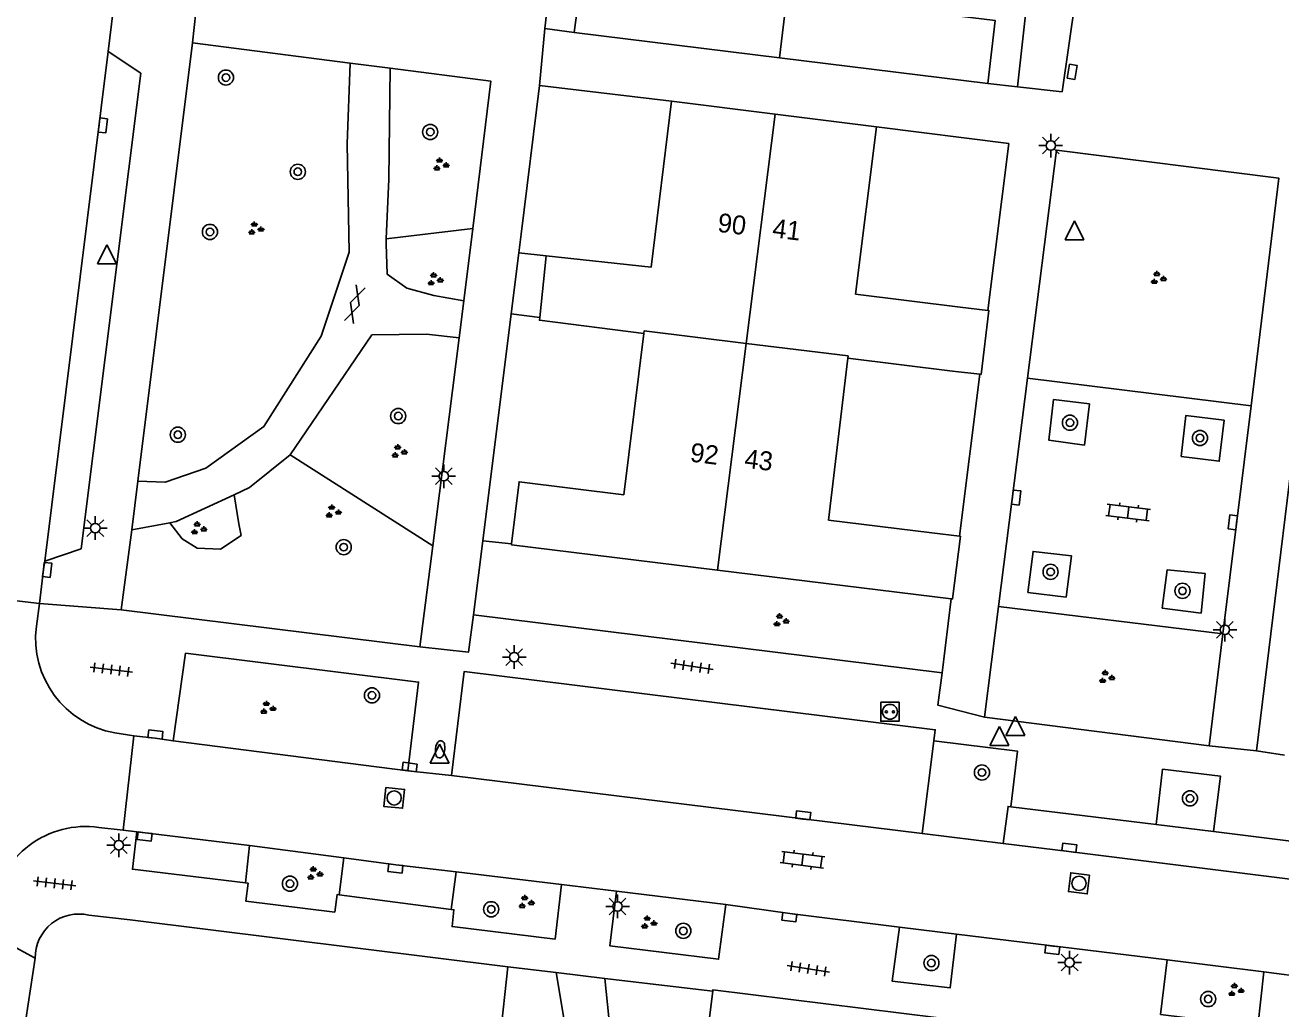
# Model space of a CAD drawing. Extents: x 131000 to 133014, y 396499 to 399001.
# Drawn here: x 131362.8 to 131429.2, y 396813.1 to 396865 of the extents above; entities that cross this region are included whole.
import ezdxf

# ---------------------------------------------------------------- set-up
doc = ezdxf.new("R2010")
doc.units = 0
for name, color, linetype in [('gg-afsc-erfafscheiding', 7, 'Continuous'), ('gg-afsc-hekwerk', 7, 'Continuous'), ('gg-afsc-muur', 7, 'Continuous'), ('gg-anno-huisnummerreeks BGT', 7, 'Continuous'), ('gg-bbg-hoofdgebouw', 7, 'Continuous'), ('gg-bbg-tussenscheiding', 7, 'Continuous'), ('gg-knt-verharding', 7, 'Continuous'), ('gg-knt-verharding nz', 7, 'Continuous'), ('gt-grn-groengrens', 7, 'Continuous'), ('gt-grn-weggrens', 7, 'Continuous'), ('gt-symb-boom', 7, 'Continuous'), ('gt-symb-brandkraan', 7, 'Continuous'), ('gt-symb-gesloten verharding', 7, 'Continuous'), ('gt-symb-groenvak', 7, 'Continuous'), ('gt-symb-klinker verharding', 7, 'Continuous'), ('gt-symb-kolk', 7, 'Continuous'), ('gt-symb-kolk center center', 7, 'Continuous'), ('gt-symb-laadpunt elektrisch vervoer', 7, 'Continuous'), ('gt-symb-lichtmast', 7, 'Continuous'), ('gt-symb-rioolschacht', 7, 'Continuous'), ('gt-symb-tegel verharding', 7, 'Continuous'), ('gt-symb-waterafsluiter', 7, 'Continuous')]:
    doc.layers.add(name, color=color, linetype=linetype)

# ---------------------------------------------------------------- blocks, each defined once
blk = doc.blocks.new('gt0-BOOM')
at = {"layer": 'gt-symb-boom'}
for radius in [0.4, 0.2]:
    blk.add_circle((0, 0), radius, dxfattribs=at)
blk = doc.blocks.new('gt0-GRVAK')
at = {"layer": 'gt-symb-groenvak'}
for p, q in [((-0.11, 0.189), (-0.228, 0.24)), ((-0.182, 0.153), (0.088, 0.153)), ((-0.091, 0.211), (-0.156, 0.322)), ((-0.047, 0.214), (-0.047, 0.393)), ((-0.004, 0.211), (0.061, 0.322)), ((0.015, 0.189), (0.133, 0.24)), ((0.262, -0.052), (0.197, 0.059)), ((0.305, -0.049), (0.305, 0.13)), ((0.349, -0.052), (0.414, 0.059)), ((-0.245, -0.228), (-0.363, -0.177)), ((-0.318, -0.264), (-0.047, -0.264)), ((-0.226, -0.206), (-0.291, -0.095)), ((-0.183, -0.203), (-0.183, -0.024)), ((-0.139, -0.206), (-0.074, -0.095)), ((-0.12, -0.228), (-0.002, -0.177)), ((0.243, -0.074), (0.125, -0.023)), ((0.17, -0.11), (0.441, -0.11)), ((0.368, -0.074), (0.486, -0.023))]:
    blk.add_line(p, q, dxfattribs=at)
blk = doc.blocks.new('gt0-LMAST')
at = {"layer": 'gt-symb-lichtmast'}
for p, q in [((-0.182, 0.173), (-0.447, 0.438)), ((-0.005, 0.246), (-0.005, 0.621)), ((0.172, 0.173), (0.437, 0.438)), ((-0.255, -0.004), (-0.63, -0.004)), ((-0.182, -0.181), (-0.447, -0.446)), ((-0.005, -0.254), (-0.005, -0.629)), ((0.437, -0.446), (0.172, -0.181)), ((0.245, -0.004), (0.62, -0.004))]:
    blk.add_line(p, q, dxfattribs=at)
blk.add_circle((-0.005, -0.004), 0.25, dxfattribs=at)
blk = doc.blocks.new('gt0-KOLK')
at = {"layer": 'gt-symb-kolk'}
blk.add_lwpolyline([(0, 0), (0.375, 0), (0.375, 0.4), (-0.375, 0.4), (-0.375, 0), (0, 0)], dxfattribs=at)
blk = doc.blocks.new('gt0-KL1')
at = {"layer": 'gt-symb-klinker verharding'}
for p, q in [((-1.15, 0.3), (1.15, 0.3)), ((-1, -0.3), (-1, 0.3)), ((-0.5, 0.3), (-0.5, 0.45)), ((0, -0.3), (0, 0.3)), ((0.5, 0.3), (0.5, 0.45)), ((1, -0.3), (1, 0.3)), ((-1.15, -0.3), (1.15, -0.3)), ((-0.5, -0.45), (-0.5, -0.3)), ((0.5, -0.45), (0.5, -0.3))]:
    blk.add_line(p, q, dxfattribs=at)
blk = doc.blocks.new('gt0-WAFSL')
at = {"layer": 'gt-symb-waterafsluiter'}
for p, q in [((-0.5, -0.333), (0, 0.667)), ((0, 0.667), (0.5, -0.333)), ((0.5, -0.333), (-0.5, -0.333))]:
    blk.add_line(p, q, dxfattribs=at)
blk = doc.blocks.new('gt0-KOLKCC')
at = {"layer": 'gt-symb-kolk center center'}
blk.add_lwpolyline([(-0.375, 0.2), (0.375, 0.2), (0.375, -0.2), (-0.375, -0.2)], close=True, dxfattribs=at)
blk = doc.blocks.new('gt0-RS')
at = {"layer": 'gt-symb-rioolschacht'}
blk.add_lwpolyline([(-0.5, -0.5), (0.5, -0.5), (0.5, 0.5), (-0.5, 0.5)], close=True, dxfattribs=at)
blk.add_circle((0, 0), 0.375, dxfattribs=at)
blk = doc.blocks.new('gt0-TEG1')
at = {"layer": 'gt-symb-tegel verharding'}
for p, q in [((-1.125, 0), (1.125, 0)), ((-0.9, -0.25), (-0.9, 0.25)), ((-0.45, -0.25), (-0.45, 0.25)), ((0, -0.25), (0, 0.25)), ((0.45, -0.25), (0.45, 0.25)), ((0.9, -0.25), (0.9, 0.25))]:
    blk.add_line(p, q, dxfattribs=at)
blk = doc.blocks.new('gt0-LEV')
at = {"layer": 'gt-symb-laadpunt elektrisch vervoer'}
blk.add_lwpolyline([(-0.486, 0.501), (0.486, 0.501), (0.486, -0.499), (-0.486, -0.499)], close=True, dxfattribs=at)
for centre, radius in [((0, 0), 0.393), ((-0.186, 0), 0.0566), ((0.186, 0), 0.0566)]:
    blk.add_circle(centre, radius, dxfattribs=at)
blk = doc.blocks.new('gt0-BR')
at = {"layer": 'gt-symb-brandkraan'}
for centre, radius, start, end in [((-0.244, 0), 0.206, 107.56694, 252.43307), ((0.599, -2.664), 3, 106.89205, 107.56694), ((0, -0.691), 0.938, 73.10799, 106.89205), ((-0.599, -2.664), 3, 72.43309, 73.10799), ((0.244, 0), 0.206, 287.56695, 72.43309), ((0.599, 2.664), 3, 252.43307, 253.10797), ((0, 0.691), 0.938, 253.10797, 286.89206), ((-0.599, 2.664), 3, 286.89206, 287.56695)]:
    blk.add_arc(centre, radius, start, end, dxfattribs=at)
blk = doc.blocks.new('gt0-GESVH1')
at = {"layer": 'gt-symb-gesloten verharding'}
for p, q in [((-0.992, -0.261), (0.008, 0.239)), ((0.008, -0.261), (-0.992, 0.239)), ((0.008, 0.239), (1.008, -0.261)), ((1.008, 0.239), (0.008, -0.261))]:
    blk.add_line(p, q, dxfattribs=at)

msp = doc.modelspace()

# ---------------------------------------------------------------- linework, layer by layer
at = {"layer": 'gg-afsc-erfafscheiding'}
for p, q in [((131397.74, 396924.6), (131390.25, 396864.87)), ((131390.25, 396864.87), (131391.81, 396864.65)), ((131414.77, 396858.79), (131413.664, 396849.974)), ((131430.695, 396849.868), (131427.87, 396826.7)), ((131413.24, 396846.596), (131412.167, 396838.045)), ((131427.87, 396826.7), (131429.35, 396826.47))]:
    msp.add_line(p, q, dxfattribs=at)
at = {"layer": 'gg-afsc-hekwerk'}
for p, q in [((131368.347, 396817.779), (131388.304, 396815.302)), ((131388.304, 396815.302), (131387.67, 396809.42))]:
    msp.add_line(p, q, dxfattribs=at)
at = {"layer": 'gg-afsc-muur'}
for p, q in [((131389.98, 396861.86), (131389.002, 396854)), ((131396.96, 396861.02), (131389.98, 396861.86)), ((131407.79, 396859.66), (131414.77, 396858.79)), ((131388.478, 396849.788), (131388.879, 396853.007)), ((131390.33, 396852.85), (131388.879, 396853.007)), ((131389.986, 396849.599), (131388.478, 396849.788))]:
    msp.add_line(p, q, dxfattribs=at)
at = {"layer": 'gg-bbg-hoofdgebouw'}
for p, q in [((131391.81, 396864.65), (131402.651, 396863.316)), ((131402.651, 396863.316), (131413.67, 396861.96)), ((131396.96, 396861.02), (131402.438, 396860.332)), ((131402.438, 396860.332), (131407.79, 396859.66)), ((131390.33, 396852.85), (131389.986, 396849.599)), ((131413.664, 396849.974), (131412.21, 396850.15)), ((131406.27, 396847.44), (131411.8, 396846.77)), ((131411.8, 396846.77), (131413.24, 396846.596)), ((131412.167, 396838.045), (131410.71, 396838.23)), ((131399.391, 396836.255), (131411.73, 396834.737))]:
    msp.add_line(p, q, dxfattribs=at)
for points in [[(131398.84, 396875.89), (131397.82, 396867.35), (131392.25, 396867.95), (131391.81, 396864.65)], [(131413.67, 396861.96), (131414.06, 396865.28), (131408.54, 396865.96), (131409.6, 396874.5)], [(131396.96, 396861.02), (131395.87, 396852.25), (131390.33, 396852.85)], [(131412.21, 396850.15), (131406.68, 396850.83), (131407.79, 396859.66)], [(131389.986, 396849.599), (131389.97, 396849.45), (131395.49, 396848.76)], [(131413.24, 396846.596), (131413.31, 396846.587), (131413.72, 396849.967), (131413.664, 396849.974)], [(131395.49, 396848.76), (131394.43, 396840.23), (131388.9, 396840.92), (131388.497, 396837.648)], [(131410.71, 396838.23), (131405.25, 396838.9), (131406.27, 396847.44)], [(131388.497, 396837.648), (131388.49, 396837.59), (131399.391, 396836.255)], [(131411.73, 396834.737), (131411.801, 396834.728), (131412.221, 396838.038), (131412.167, 396838.045)], [(131399.13, 396814.01), (131396.65, 396794.23), (131403.55, 396793.37)], [(131415.066, 396812.112), (131399.14, 396814.09), (131399.13, 396814.01)]]:
    msp.add_lwpolyline(points, dxfattribs=at)
at = {"layer": 'gg-bbg-tussenscheiding'}
for p, q in [((131404.122, 396875.241), (131402.651, 396863.316)), ((131402.438, 396860.332), (131400.906, 396848.228)), ((131400.906, 396848.228), (131399.391, 396836.255))]:
    msp.add_line(p, q, dxfattribs=at)
for points in [[(131400.906, 396848.228), (131395.506, 396848.889), (131395.49, 396848.76)], [(131400.906, 396848.228), (131406.285, 396847.569), (131406.27, 396847.44)]]:
    msp.add_lwpolyline(points, dxfattribs=at)
at = {"layer": 'gg-knt-verharding'}
for p, q in [((131367.182, 396863.652), (131367.798, 396868.619)), ((131415.79, 396866.747), (131415.234, 396861.783)), ((131368.757, 396840.943), (131371.64, 396864.1)), ((131371.64, 396864.1), (131379.966, 396863.033)), ((131379.966, 396863.033), (131382.084, 396862.762)), ((131415.234, 396861.783), (131413.67, 396861.96)), ((131385.971, 396850.479), (131386.445, 396854.302)), ((131388.879, 396853.007), (131389.002, 396854)), ((131385.971, 396850.479), (131385.727, 396848.514)), ((131386.976, 396837.801), (131388.478, 396849.788)), ((131384.333, 396837.53), (131385.727, 396848.514)), ((131414.24, 396834.33), (131415.77, 396846.4)), ((131415.77, 396846.4), (131427.59, 396844.93)), ((131427.59, 396844.93), (131426.08, 396832.89)), ((131368.438, 396838.379), (131368.757, 396840.943)), ((131368.438, 396838.379), (131367.866, 396834.16)), ((131368.438, 396838.379), (131370.435, 396838.752)), ((131383.657, 396832.201), (131384.333, 396837.53)), ((131386.487, 396833.899), (131386.976, 396837.801)), ((131388.497, 396837.648), (131386.976, 396837.801)), ((131356.473, 396835.344), (131363.548, 396834.487)), ((131363.548, 396834.487), (131363.387, 396833.286)), ((131411.73, 396834.737), (131411.248, 396830.823)), ((131413.5, 396828.48), (131414.24, 396834.33)), ((131426.08, 396832.89), (131414.24, 396834.33)), ((131367.866, 396834.16), (131383.657, 396832.201)), ((131411.248, 396830.823), (131386.487, 396833.899)), ((131426.08, 396832.89), (131425.37, 396826.97)), ((131425.37, 396826.97), (131413.5, 396828.48)), ((131367.539, 396827.657), (131368.542, 396827.5)), ((131367.969, 396822.519), (131368.542, 396827.5)), ((131383.013, 396825.658), (131370.617, 396827.235)), ((131410.813, 396827.237), (131410.19, 396822.336)), ((131385.332, 396825.401), (131383.013, 396825.658)), ((131414.886, 396823.751), (131422.563, 396822.82)), ((131367.969, 396822.519), (131366.684, 396822.66)), ((131368.689, 396822.434), (131367.969, 396822.519)), ((131410.19, 396822.336), (131414.479, 396821.807)), ((131425.592, 396822.452), (131422.563, 396822.82)), ((131425.592, 396822.452), (131432.988, 396821.525)), ((131374.657, 396821.706), (131374.435, 396819.73)), ((131379.64, 396821.064), (131374.657, 396821.706)), ((131379.395, 396819.095), (131379.64, 396821.064)), ((131385.307, 396818.332), (131385.571, 396820.322)), ((131385.571, 396820.322), (131391.137, 396819.642)), ((131391.137, 396819.642), (131394.042, 396819.299)), ((131385.307, 396818.332), (131379.395, 396819.095)), ((131394.042, 396819.299), (131399.823, 396818.593)), ((131366.16, 396818.027), (131368.347, 396817.779)), ((131408.992, 396817.396), (131412.006, 396817.025)), ((131412.006, 396817.025), (131423.151, 396815.659)), ((131362.826, 396812.521), (131363.324, 396815.75)), ((131423.151, 396815.659), (131428.255, 396815.027)), ((131388.304, 396815.302), (131390.854, 396814.998)), ((131390.854, 396814.998), (131393.43, 396814.69)), ((131428.255, 396815.027), (131439.526, 396813.605)), ((131393.43, 396814.69), (131399.13, 396814.01))]:
    msp.add_line(p, q, dxfattribs=at)
for points in [[(131415.234, 396861.783), (131417.592, 396861.518), (131418.293, 396866.436), (131415.79, 396866.747)], [(131363.84, 396836.732), (131365.753, 396837.383), (131368.908, 396862.502), (131367.182, 396863.652)], [(131379.966, 396863.033), (131379.805, 396858.763), (131379.911, 396853.052), (131378.433, 396848.607), (131375.414, 396843.839), (131372.337, 396841.634), (131370.201, 396840.907), (131368.757, 396840.943)], [(131381.876, 396853.758), (131382.007, 396856.908), (131382.084, 396862.762)], [(131386.445, 396854.302), (131387.41, 396862.08), (131382.084, 396862.762)], [(131415.77, 396846.4), (131417.29, 396858.44), (131429.04, 396856.96), (131427.59, 396844.93)], [(131385.971, 396850.479), (131384.386, 396850.761), (131382.971, 396851.15), (131381.933, 396851.884), (131381.865, 396853.493), (131381.876, 396853.758)], [(131376.804, 396842.335), (131381.117, 396848.676), (131384.012, 396848.724), (131385.727, 396848.514)], [(131418.775, 396842.861), (131416.895, 396843.112), (131417.146, 396845.259), (131419.033, 396845.029), (131418.775, 396842.861)], [(131423.876, 396842.258), (131425.899, 396842.001), (131426.157, 396844.166), (131424.134, 396844.423), (131423.876, 396842.258)], [(131373.838, 396840.238), (131374.648, 396840.615), (131376.804, 396842.335)], [(131370.435, 396838.752), (131370.783, 396838.817), (131373.838, 396840.238)], [(131415.779, 396835.075), (131416.057, 396837.245), (131418.09, 396837.002), (131417.802, 396834.832), (131415.779, 396835.075)], [(131363.548, 396834.487), (131363.764, 396836.289), (131363.84, 396836.732)], [(131422.878, 396834.251), (131423.146, 396836.276), (131425.146, 396836.074), (131424.936, 396833.983), (131422.878, 396834.251)], [(131370.617, 396827.235), (131371.273, 396831.863), (131383.584, 396830.34), (131383.013, 396825.658)], [(131385.332, 396825.401), (131385.992, 396830.893), (131410.887, 396827.817), (131410.813, 396827.237)], [(131368.542, 396827.5), (131369.66, 396827.372), (131370.617, 396827.235)], [(131414.886, 396823.751), (131415.23, 396826.695), (131410.813, 396827.237)], [(131422.563, 396822.82), (131422.906, 396825.738), (131425.959, 396825.374), (131425.592, 396822.452)], [(131414.479, 396821.807), (131414.742, 396823.768), (131414.886, 396823.751)], [(131374.435, 396819.73), (131368.464, 396820.449), (131368.689, 396822.434)], [(131379.395, 396819.095), (131379.277, 396819.11), (131379.157, 396818.192), (131374.451, 396818.767), (131374.573, 396819.713), (131374.435, 396819.73)], [(131391.137, 396819.642), (131390.796, 396816.763), (131385.355, 396817.423), (131385.453, 396818.313), (131385.307, 396818.332)], [(131399.823, 396818.593), (131399.443, 396815.699), (131393.694, 396816.406), (131394.042, 396819.299)], [(131399.823, 396818.593), (131403.206, 396818.115), (131408.992, 396817.396)], [(131412.006, 396817.025), (131411.673, 396814.182), (131408.619, 396814.539), (131408.992, 396817.396)], [(131428.255, 396815.027), (131427.934, 396812.146), (131422.798, 396812.784), (131423.151, 396815.659)], [(131390.854, 396814.998), (131392.07, 396807.72), (131392.4, 396803.51), (131392.37, 396800.36), (131392.264, 396799.866)], [(131392.37, 396792.3), (131393.26, 396795.58), (131393.85, 396797.56), (131394.36, 396800.24), (131394.46, 396802.02), (131394.46, 396804.43), (131394.28, 396807.55), (131393.87, 396810.39), (131393.43, 396814.69)]]:
    msp.add_lwpolyline(points, dxfattribs=at)
for centre, radius, start, end in [((131368.419, 396832.652), 5.072, 172.82054, 260.00509), ((131365.982, 396817.793), 4.917, 81.7975, 172.42739), ((131365.633, 396815.779), 2.309, 76.81358, 180.70778)]:
    msp.add_arc(centre, radius, start, end, dxfattribs=at)
at = {"layer": 'gg-knt-verharding nz'}
for p, q in [((131363.84, 396836.732), (131367.182, 396863.652)), ((131410.19, 396822.336), (131385.332, 396825.401)), ((131368.689, 396822.434), (131374.657, 396821.706))]:
    msp.add_line(p, q, dxfattribs=at)
for points in [[(131455.889, 396816.625), (131447.389, 396817.711), (131417.954, 396821.389), (131414.479, 396821.807)], [(131385.571, 396820.322), (131382.385, 396820.689), (131379.64, 396821.064)]]:
    msp.add_lwpolyline(points, dxfattribs=at)
at = {"layer": 'gt-grn-groengrens'}
for p, q in [((131381.876, 396853.758), (131386.445, 396854.302)), ((131384.333, 396837.53), (131376.804, 396842.335))]:
    msp.add_line(p, q, dxfattribs=at)
msp.add_lwpolyline([(131373.838, 396840.238), (131374.087, 396838.696), (131374.209, 396838.086), (131373.11, 396837.353), (131371.889, 396837.414), (131371.095, 396837.902), (131370.435, 396838.752)], dxfattribs=at)
at = {"layer": 'gt-grn-weggrens'}
for p, q in [((131371.98, 396867.21), (131371.64, 396864.1)), ((131389.98, 396861.86), (131390.25, 396864.87)), ((131363.548, 396834.487), (131367.866, 396834.16)), ((131425.37, 396826.97), (131427.87, 396826.7)), ((131360.896, 396817.057), (131363.324, 396815.75))]:
    msp.add_line(p, q, dxfattribs=at)
for points in [[(131383.657, 396832.201), (131386.221, 396831.914), (131386.487, 396833.899)], [(131413.5, 396828.48), (131411.022, 396829.123), (131411.248, 396830.823)]]:
    msp.add_lwpolyline(points, dxfattribs=at)

# ---------------------------------------------------------------- block references
at = {"layer": 'gt-symb-boom'}
for p in [(131373.405, 396862.27), (131384.202, 396859.396), (131377.204, 396857.294), (131372.56, 396854.116), (131418.006, 396844.04), (131370.864, 396843.405), (131424.878, 396843.232), (131379.629, 396837.465), (131416.984, 396836.16), (131423.955, 396835.158), (131381.122, 396829.636), (131413.358, 396825.563), (131424.349, 396824.196), (131376.788, 396819.69), (131387.423, 396818.338), (131397.577, 396817.196), (131410.687, 396815.498), (131425.311, 396813.595)]:
    msp.add_blockref('gt0-BOOM', p, dxfattribs=at)
at = {"layer": 'gt-symb-boom', "rotation": 82.8749836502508}
msp.add_blockref('gt0-BOOM', (131382.511, 396844.39), dxfattribs=at)
at = {"layer": 'gt-symb-brandkraan', "rotation": 83.3370363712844}
msp.add_blockref('gt0-BR', (131384.725, 396826.79), dxfattribs=at)
at = {"layer": 'gt-symb-gesloten verharding', "rotation": 71.5831655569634}
msp.add_blockref('gt0-GESVH1', (131380.204, 396850.298), dxfattribs=at)
at = {"layer": 'gt-symb-groenvak'}
for p in [(131384.737, 396857.664), (131374.953, 396854.282), (131384.43, 396851.597), (131422.648, 396851.667), (131382.529, 396842.509), (131379.045, 396839.33), (131371.931, 396838.445), (131402.709, 396833.587), (131419.919, 396830.592), (131375.589, 396828.962), (131378.071, 396820.216), (131389.242, 396818.704), (131395.717, 396817.624), (131426.746, 396814.061)]:
    msp.add_blockref('gt0-GRVAK', p, dxfattribs=at)
at = {"layer": 'gt-symb-klinker verharding'}
for p, rotation in [((131421.082, 396839.299), -7.068140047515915), ((131403.878, 396820.955), -7.125016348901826)]:
    msp.add_blockref('gt0-KL1', p, dxfattribs=dict(at, rotation=rotation))
at = {"layer": 'gt-symb-kolk'}
for p, rotation in [((131366.702, 396859.765), -97.12501634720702), ((131414.97, 396840.11), -96.89054832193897), ((131426.813, 396838.754), 82.81812146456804), ((131363.764, 396836.289), -96.83367234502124), ((131369.66, 396827.372), -6.485660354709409), ((131383.085, 396825.654), -7.8141808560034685), ((131403.889, 396823.103), -6.947410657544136), ((131369.135, 396822.378), 173.5143396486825), ((131417.954, 396821.389), -7.125016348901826), ((131382.385, 396820.689), 173.45090842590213), ((131403.206, 396818.115), 171.95093829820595), ((131417.097, 396816.393), 172.93185994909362)]:
    msp.add_blockref('gt0-KOLK', p, dxfattribs=dict(at, rotation=rotation))
at = {"layer": 'gt-symb-kolk center center', "rotation": 81.00597824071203}
msp.add_blockref('gt0-KOLKCC', (131418.125, 396862.572), dxfattribs=at)
at = {"layer": 'gt-symb-laadpunt elektrisch vervoer'}
msp.add_blockref('gt0-LEV', (131408.493, 396828.769), dxfattribs=at)
at = {"layer": 'gt-symb-lichtmast'}
for p in [(131417.002, 396858.684), (131384.919, 396841.217), (131366.508, 396838.478), (131426.202, 396833.106), (131388.646, 396831.662), (131367.747, 396821.723), (131394.105, 396818.492), (131417.996, 396815.528)]:
    msp.add_blockref('gt0-LMAST', p, dxfattribs=at)
at = {"layer": 'gt-symb-rioolschacht'}
for p, rotation in [((131382.297, 396824.221), -95.85309129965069), ((131418.486, 396819.708), 173.22321716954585)]:
    msp.add_blockref('gt0-RS', p, dxfattribs=dict(at, rotation=rotation))
at = {"layer": 'gt-symb-tegel verharding'}
for p, rotation in [((131398.033, 396831.166), -8.340866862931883), ((131367.346, 396830.997), -7.0042592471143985), ((131364.349, 396819.708), -6.485660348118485), ((131404.183, 396815.192), -8.916036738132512)]:
    msp.add_blockref('gt0-TEG1', p, dxfattribs=dict(at, rotation=rotation))
at = {"layer": 'gt-symb-waterafsluiter'}
for p in [(131418.246, 396854.038), (131367.119, 396852.762), (131415.125, 396827.85), (131414.28, 396827.324), (131384.698, 396826.387)]:
    msp.add_blockref('gt0-WAFSL', p, dxfattribs=at)

# ---------------------------------------------------------------- texts
at = {"layer": 'gg-anno-huisnummerreeks BGT'}
for s, rotation, p in [('90', 352.9, (131399.351, 396854.128)), ('41', 352.8, (131402.243, 396853.84)), ('92', 352.9, (131397.897, 396841.993)), ('43', 353.2, (131400.77, 396841.663))]:
    msp.add_text(s, height=1, rotation=rotation, dxfattribs=at).set_placement(p)

doc.saveas('drawing.dxf')
